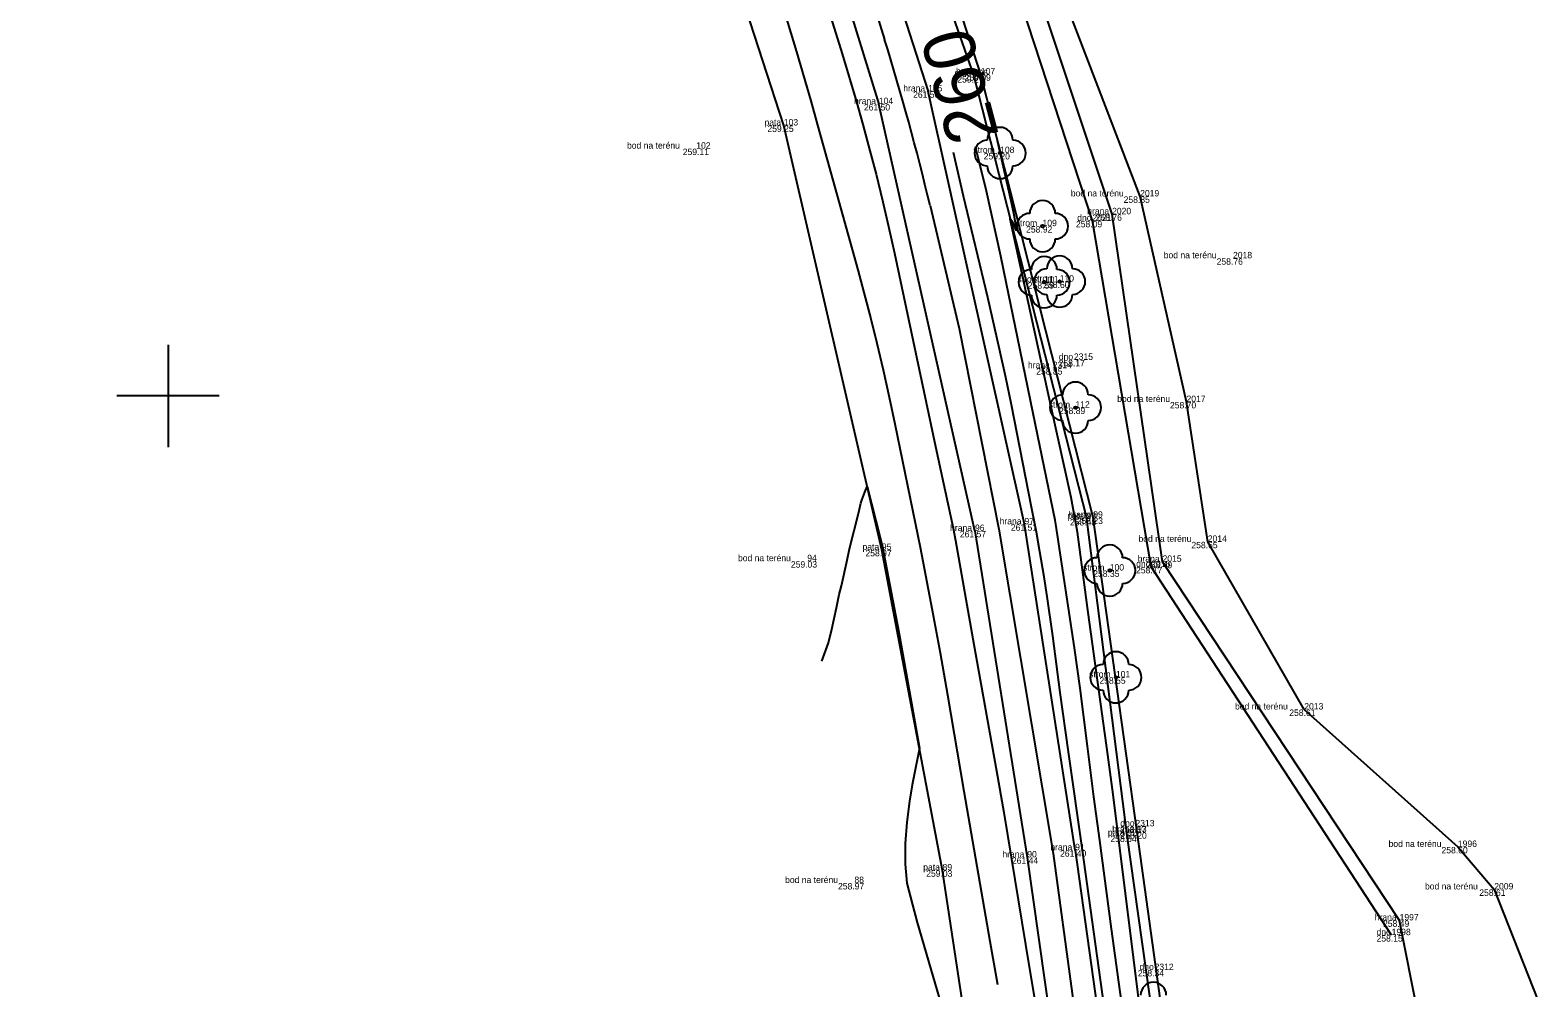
# Model space of a CAD drawing. Extents: x -567962 to -566460, y -1093720 to -1089838.
# Drawn here: x -567610.8 to -567493.1, y -1093446.2 to -1093371.4 of the extents above; entities that cross this region are included whole.
import ezdxf

# ---------------------------------------------------------------- set-up
doc = ezdxf.new("R2010")
doc.units = 0
for name, color, linetype in [('0_osa hráze', 7, 'Continuous'), ('bod_znacka', 7, 'Continuous'), ('cislo_bodu', 7, 'Continuous'), ('ctvercova_sit', 7, 'Continuous'), ('Doměření - kraj pole', 7, 'Continuous'), ('hlavni_vrst', 7, 'Continuous'), ('hrana_L', 7, 'Continuous'), ('kod_bodu', 7, 'Continuous'), ('norm_vrst', 7, 'Continuous'), ('Popis_hl_vrs', 7, 'Continuous'), ('stromy', 7, 'Continuous'), ('vyska_bodu', 7, 'Continuous')]:
    doc.layers.add(name, color=color, linetype=linetype)

msp = doc.modelspace()

# ---------------------------------------------------------------- linework, layer by layer
at = {"layer": '0_osa hráze'}
for points in [[(-567550.67, -1093350.89), (-567544.08, -1093372.16)], [(-567540.53, -1093385.13), (-567538.25, -1093394.72), (-567535.17, -1093410.4), (-567530.93, -1093435.73), (-567525.97, -1093472.15), (-567525.38, -1093480.07)]]:
    msp.add_lwpolyline(points, dxfattribs=at)
msp.add_arc((-567735.11, -1093431.38), 200, 13.3699, 17.225, dxfattribs=at)
at = {"layer": 'bod_znacka'}
for p, q in [((-567537.12, -1093375.03), (-567537.12, -1093375.03)), ((-567536.56, -1093374.89), (-567536.56, -1093374.89)), ((-567540.68, -1093376.22), (-567540.68, -1093376.22)), ((-567544.52, -1093377.21), (-567544.52, -1093377.21)), ((-567551.94, -1093378.88), (-567551.94, -1093378.88)), ((-567558.77, -1093380.69), (-567558.77, -1093380.69)), ((-567535.06, -1093381.03), (-567535.06, -1093381.03)), ((-567524.13, -1093384.42), (-567524.13, -1093384.42)), ((-567527.86, -1093386.33), (-567527.86, -1093386.33)), ((-567526.32, -1093385.81), (-567526.32, -1093385.81)), ((-567531.75, -1093386.74), (-567531.75, -1093386.74)), ((-567516.88, -1093389.25), (-567516.88, -1093389.25)), ((-567531.62, -1093391.12), (-567531.62, -1093391.12)), ((-567530.41, -1093391.07), (-567530.41, -1093391.07)), ((-567530.95, -1093397.83), (-567530.95, -1093397.83)), ((-567529.3, -1093397.18), (-567529.3, -1093397.18)), ((-567520.51, -1093400.47), (-567520.51, -1093400.47)), ((-567529.18, -1093400.91), (-567529.18, -1093400.91)), ((-567533.16, -1093410.02), (-567533.16, -1093410.02)), ((-567528.3, -1093409.61), (-567528.3, -1093409.61)), ((-567527.79, -1093409.5), (-567527.79, -1093409.5)), ((-567537.02, -1093410.54), (-567537.02, -1093410.54)), ((-567544.29, -1093412.02), (-567544.29, -1093412.02)), ((-567518.85, -1093411.39), (-567518.85, -1093411.39)), ((-567550.11, -1093412.9), (-567550.11, -1093412.9)), ((-567523.26, -1093413.35), (-567523.26, -1093413.35)), ((-567522.38, -1093412.95), (-567522.38, -1093412.95)), ((-567526.5, -1093413.63), (-567526.5, -1093413.63)), ((-567526.02, -1093421.97), (-567526.02, -1093421.97)), ((-567511.32, -1093424.48), (-567511.32, -1093424.48)), ((-567524.5, -1093433.6), (-567524.5, -1093433.6)), ((-567525.14, -1093434.33), (-567525.14, -1093434.33)), ((-567524.37, -1093434.07), (-567524.37, -1093434.07)), ((-567529.2, -1093435.47), (-567529.2, -1093435.47)), ((-567499.33, -1093435.21), (-567499.33, -1093435.21)), ((-567539.55, -1093437.04), (-567539.55, -1093437.04)), ((-567532.94, -1093436.03), (-567532.94, -1093436.03)), ((-567546.43, -1093438.03), (-567546.43, -1093438.03)), ((-567496.49, -1093438.53), (-567496.49, -1093438.53)), ((-567503.88, -1093440.95), (-567503.88, -1093440.95)), ((-567504.5, -1093442.1), (-567504.5, -1093442.1)), ((-567523, -1093444.82), (-567523, -1093444.82))]:
    msp.add_line(p, q, dxfattribs=at)
at = {"layer": 'ctvercova_sit'}
for points in [[(-567600, -1093396), (-567600, -1093404)], [(-567596, -1093400), (-567604, -1093400)]]:
    msp.add_lwpolyline(points, dxfattribs=at)
at = {"layer": 'Doměření - kraj pole'}
for points in [[(-567511.32, -1093424.48), (-567518.85, -1093411.39), (-567520.51, -1093400.47), (-567524.13, -1093384.42), (-567533.3, -1093360.45), (-567540.81, -1093336.06), (-567555.22, -1093294.34), (-567607.1, -1093144.72), (-567617.83, -1093113.35), (-567634.56, -1093065.71), (-567666.8, -1092973.41), (-567707.16, -1092860.34), (-567710.41, -1092851.09), (-567718.35, -1092825.43), (-567724.94, -1092789.73), (-567726.76, -1092756.76), (-567722.48, -1092688.96)], [(-567511.32, -1093424.48), (-567499.33, -1093435.21), (-567496.49, -1093438.53), (-567493.09, -1093447.18), (-567494.5, -1093456.59), (-567505.65, -1093469.6), (-567507.9, -1093475.55), (-567510.24, -1093490.41)]]:
    msp.add_lwpolyline(points, dxfattribs=at)
at = {"layer": 'hlavni_vrst'}
for points in [[(-567552.09, -1093369.36), (-567550.96, -1093373.14), (-567549.84, -1093376.95), (-567549.3, -1093378.86), (-567546.17, -1093390.14), (-567545.69, -1093391.91), (-567545.15, -1093393.97), (-567544.67, -1093395.88), (-567544.18, -1093397.96), (-567543.71, -1093400.09), (-567543.27, -1093402.17), (-567541.47, -1093410.93), (-567541.3, -1093411.8), (-567540.36, -1093416.73), (-567539.74, -1093420.06), (-567539.16, -1093423.34), (-567537.9, -1093430.85), (-567535.86, -1093442.57), (-567535.26, -1093445.96)], [(-567525.41, -1093448.61), (-567526.37, -1093441.6), (-567527.28, -1093434.7), (-567527.74, -1093431.31), (-567528.24, -1093427.34), (-567528.81, -1093422.82), (-567529.25, -1093419.66), (-567530.23, -1093413.11), (-567530.71, -1093410.02), (-567530.77, -1093409.69), (-567532.3, -1093402.26), (-567533.88, -1093394.53), (-567534.56, -1093391.25), (-567535.01, -1093389.08), (-567536.13, -1093384.01), (-567536.98, -1093380.54)]]:
    msp.add_lwpolyline(points, dxfattribs=at)
at = {"layer": 'hrana_L'}
for p, q in [((-567547.59, -1093345.05), (-567537.12, -1093375.03)), ((-567536.56, -1093374.89), (-567546.32, -1093344.74)), ((-567550.25, -1093346.34), (-567540.68, -1093376.22)), ((-567553.65, -1093347.55), (-567544.52, -1093377.21)), ((-567551.94, -1093378.88), (-567561.12, -1093350.53)), ((-567537.12, -1093375.03), (-567528.3, -1093409.61)), ((-567527.79, -1093409.5), (-567536.56, -1093374.89)), ((-567533.16, -1093410.02), (-567540.68, -1093376.22)), ((-567537.02, -1093410.54), (-567544.52, -1093377.21)), ((-567544.29, -1093412.02), (-567551.94, -1093378.88)), ((-567529.2, -1093435.47), (-567533.16, -1093410.02)), ((-567525.14, -1093434.33), (-567528.3, -1093409.61)), ((-567524.37, -1093434.07), (-567527.79, -1093409.5)), ((-567537.02, -1093410.54), (-567532.94, -1093436.03)), ((-567539.55, -1093437.04), (-567544.29, -1093412.02)), ((-567521.13, -1093462.82), (-567525.14, -1093434.33)), ((-567520.34, -1093462.89), (-567524.37, -1093434.07)), ((-567529.2, -1093435.47), (-567525.27, -1093463.58)), ((-567535.31, -1093465.11), (-567539.55, -1093437.04)), ((-567532.94, -1093436.03), (-567528.96, -1093464.11))]:
    msp.add_line(p, q, dxfattribs=at)
for points in [[(-567504.5, -1093442.1), (-567523.26, -1093413.35), (-567527.86, -1093386.33), (-567536.4, -1093360.17), (-567544.7, -1093335.63), (-567557.74, -1093295.13), (-567579.04, -1093235.03), (-567610.15, -1093146.43), (-567637.79, -1093066.78), (-567669.86, -1092975.82), (-567712.89, -1092852.93), (-567721.73, -1092825.85), (-567728.15, -1092790.55), (-567729.9, -1092755.99), (-567725.95, -1092688.52)], [(-567512.79, -1093499.42), (-567512.53, -1093490.77), (-567515.14, -1093473.2), (-567516.86, -1093463), (-567517.05, -1093457.43), (-567510.86, -1093456.87), (-567507.33, -1093455.1), (-567502.54, -1093450.69), (-567502.42, -1093448.31), (-567503.88, -1093440.95), (-567522.38, -1093412.95), (-567526.32, -1093385.81), (-567534.77, -1093360.4), (-567542.63, -1093336.01), (-567576.2, -1093233.72), (-567608.17, -1093145.58), (-567635.77, -1093066.14), (-567667.57, -1092974.74), (-567711.16, -1092852.65), (-567720.26, -1092825.93), (-567727.08, -1092790.56), (-567728.5, -1092756.42), (-567723.8, -1092688.57)]]:
    msp.add_lwpolyline(points, dxfattribs=at)
at = {"layer": 'norm_vrst'}
for points in [[(-567551.98, -1093358.49), (-567547.4, -1093373.28), (-567546.27, -1093377.03), (-567545.77, -1093378.81), (-567545.22, -1093380.87), (-567544.74, -1093382.67), (-567544.23, -1093384.74), (-567543.76, -1093386.77), (-567543.3, -1093388.86), (-567540.09, -1093403.95), (-567538.72, -1093410.31), (-567538.53, -1093411.29), (-567537.1, -1093419.41), (-567535.33, -1093429.28), (-567534.77, -1093432.53), (-567532.79, -1093444.58), (-567531.26, -1093453.73)], [(-567523.96, -1093449.25), (-567526.24, -1093431.12), (-567526.64, -1093428.01), (-567528.19, -1093416.9), (-567529.01, -1093410.64), (-567529.52, -1093407.94), (-567531.11, -1093400.75), (-567534.27, -1093386.19), (-567534.27, -1093386.14), (-567534.21, -1093386.22), (-567534.15, -1093386.33), (-567533.82, -1093387.06), (-567533.79, -1093387.03), (-567533.78, -1093386.94), (-567533.96, -1093385.88), (-567534.11, -1093385.13), (-567534.61, -1093382.94), (-567535.27, -1093380.09)], [(-567526.68, -1093449.51), (-567528.13, -1093439.02), (-567528.63, -1093435.47), (-567529.73, -1093427.79), (-567530.37, -1093423.16), (-567530.95, -1093418.74), (-567531.38, -1093415.67), (-567531.63, -1093414.11), (-567531.95, -1093412.18), (-567532.23, -1093410.64), (-567532.6, -1093408.67), (-567534.17, -1093400.68), (-567534.62, -1093398.55), (-567535.1, -1093396.34), (-567536.03, -1093392.32), (-567537.91, -1093384.39), (-567538.7, -1093381)], [(-567548.97, -1093420.71), (-567548.46, -1093419.28), (-567548.2, -1093418.2), (-567547.82, -1093416.54), (-567547.61, -1093415.49), (-567547.45, -1093414.82), (-567547.01, -1093412.81), (-567546.81, -1093411.94), (-567546.12, -1093409.18), (-567545.93, -1093408.37), (-567545.85, -1093408.13), (-567545.62, -1093407.52), (-567545.43, -1093407.08), (-567544.76, -1093409.72), (-567544.25, -1093411.78), (-567543.55, -1093415.33), (-567542.97, -1093418.44), (-567542.14, -1093423.09), (-567541.36, -1093427.51), (-567541.92, -1093430.37), (-567542.12, -1093431.65), (-567542.34, -1093433.29), (-567542.46, -1093434.95), (-567542.47, -1093436.56), (-567542.33, -1093438.03), (-567541.9, -1093439.73), (-567541.54, -1093441.11), (-567540.3, -1093445.29), (-567539.51, -1093448.05)]]:
    msp.add_lwpolyline(points, dxfattribs=at)
at = {"layer": 'stromy'}
for centre in [(-567535.06, -1093381.03), (-567531.75, -1093386.74), (-567531.62, -1093391.12), (-567530.41, -1093391.07), (-567529.18, -1093400.91), (-567526.5, -1093413.63), (-567526.02, -1093421.97)]:
    msp.add_circle(centre, 0.1, dxfattribs=at)
for centre, start, end in [((-567535.06, -1093380.03), 0, 180), ((-567536.06, -1093381.03), 90, 270), ((-567534.06, -1093381.03), 270, 90), ((-567535.06, -1093382.03), 180, 0), ((-567531.75, -1093385.74), 0, 180), ((-567532.75, -1093386.74), 90, 270), ((-567530.75, -1093386.74), 270, 90), ((-567531.75, -1093387.74), 180, 0), ((-567531.62, -1093390.12), 0, 180), ((-567531.41, -1093391.07), 90, 270), ((-567530.41, -1093390.07), 0, 180), ((-567529.41, -1093391.07), 270, 90), ((-567532.62, -1093391.12), 90, 270), ((-567530.62, -1093391.12), 270, 90), ((-567531.62, -1093392.12), 180, 0), ((-567530.41, -1093392.07), 180, 0), ((-567529.18, -1093399.91), 0, 180), ((-567530.18, -1093400.91), 90, 270), ((-567528.18, -1093400.91), 270, 90), ((-567529.18, -1093401.91), 180, 0), ((-567526.5, -1093412.63), 0, 180), ((-567527.5, -1093413.63), 90, 270), ((-567525.5, -1093413.63), 270, 90), ((-567526.5, -1093414.63), 180, 0), ((-567526.02, -1093420.97), 0, 180), ((-567527.02, -1093421.97), 90, 270), ((-567525.02, -1093421.97), 270, 90), ((-567526.02, -1093422.97), 180, 0), ((-567523.09, -1093446.78), 0, 180)]:
    msp.add_arc(centre, 1, start, end, dxfattribs=at)

# ---------------------------------------------------------------- texts
at = {"layer": 'cislo_bodu'}
for s, p in [('106', (-567537.12, -1093375.03)), ('107', (-567536.56, -1093374.89)), ('105', (-567540.68, -1093376.22)), ('104', (-567544.52, -1093377.21)), ('103', (-567551.94, -1093378.88)), ('102', (-567558.77, -1093380.69)), ('108', (-567535.06, -1093381.03)), ('2019', (-567524.13, -1093384.42)), ('2020', (-567526.32, -1093385.81)), ('109', (-567531.75, -1093386.74)), ('2021', (-567527.86, -1093386.33)), ('2018', (-567516.88, -1093389.25)), ('111', (-567531.62, -1093391.12)), ('110', (-567530.41, -1093391.07)), ('2315', (-567529.3, -1093397.18)), ('2314', (-567530.95, -1093397.83)), ('112', (-567529.18, -1093400.91)), ('2017', (-567520.51, -1093400.47)), ('96', (-567537.02, -1093410.54)), ('97', (-567533.16, -1093410.02)), ('98', (-567528.3, -1093409.61)), ('99', (-567527.79, -1093409.5)), ('2014', (-567518.85, -1093411.39)), ('94', (-567550.11, -1093412.9)), ('95', (-567544.29, -1093412.02)), ('2015', (-567522.38, -1093412.95)), ('100', (-567526.5, -1093413.63)), ('2016', (-567523.26, -1093413.35)), ('101', (-567526.02, -1093421.97)), ('2013', (-567511.32, -1093424.48)), ('2313', (-567524.5, -1093433.6)), ('93', (-567524.37, -1093434.07)), ('92', (-567525.14, -1093434.33)), ('1996', (-567499.33, -1093435.21)), ('90', (-567532.94, -1093436.03)), ('91', (-567529.2, -1093435.47)), ('89', (-567539.55, -1093437.04)), ('88', (-567546.43, -1093438.03)), ('2009', (-567496.49, -1093438.53)), ('1997', (-567503.88, -1093440.95)), ('1998', (-567504.5, -1093442.1)), ('2312', (-567523, -1093444.82))]:
    msp.add_text(s, height=0.5, dxfattribs=at).set_placement(p)
at = {"layer": 'kod_bodu'}
for s, p in [('pata', (-567538.63, -1093375.03)), ('hrana', (-567538.5, -1093374.89)), ('hrana', (-567542.62, -1093376.22)), ('hrana', (-567546.46, -1093377.21)), ('pata', (-567553.45, -1093378.88)), ('bod na terénu', (-567564.18, -1093380.69)), ('strom', (-567537.15, -1093381.03)), ('bod na terénu', (-567529.54, -1093384.42)), ('hrana', (-567528.26, -1093385.81)), ('strom', (-567533.84, -1093386.74)), ('dno', (-567529.04, -1093386.33)), ('bod na terénu', (-567522.29, -1093389.25)), ('strom', (-567533.71, -1093391.12)), ('strom', (-567532.5, -1093391.07)), ('dno', (-567530.48, -1093397.18)), ('hrana', (-567532.89, -1093397.83)), ('strom', (-567531.27, -1093400.91)), ('bod na terénu', (-567525.92, -1093400.47)), ('hrana', (-567538.96, -1093410.54)), ('hrana', (-567535.1, -1093410.02)), ('pata', (-567529.81, -1093409.61)), ('hrana', (-567529.73, -1093409.5)), ('bod na terénu', (-567524.26, -1093411.39)), ('bod na terénu', (-567555.52, -1093412.9)), ('pata', (-567545.8, -1093412.02)), ('hrana', (-567524.32, -1093412.95)), ('strom', (-567528.59, -1093413.63)), ('dno', (-567524.44, -1093413.35)), ('strom', (-567528.11, -1093421.97)), ('bod na terénu', (-567516.73, -1093424.48)), ('hrana', (-567526.31, -1093434.07)), ('dno', (-567525.68, -1093433.6)), ('pata', (-567526.65, -1093434.33)), ('bod na terénu', (-567504.74, -1093435.21)), ('hrana', (-567534.88, -1093436.03)), ('hrana', (-567531.14, -1093435.47)), ('pata', (-567541.06, -1093437.04)), ('bod na terénu', (-567551.84, -1093438.03)), ('bod na terénu', (-567501.9, -1093438.53)), ('hrana', (-567505.82, -1093440.95)), ('dno', (-567505.68, -1093442.1)), ('dno', (-567524.18, -1093444.82))]:
    msp.add_text(s, height=0.5, dxfattribs=at).set_placement(p)
at = {"layer": 'Popis_hl_vrs'}
msp.add_text('260', height=4, rotation=104.8639, dxfattribs=at).set_placement((-567535.14, -1093379.64))
at = {"layer": 'vyska_bodu'}
for s, p in [('259.27', (-567538.4, -1093375.53)), ('259.09', (-567537.83, -1093375.39)), ('261.50', (-567541.85, -1093376.72)), ('261.50', (-567545.69, -1093377.71)), ('259.25', (-567553.22, -1093379.38)), ('259.11', (-567559.83, -1093381.19)), ('259.20', (-567536.34, -1093381.53)), ('258.85', (-567525.42, -1093384.92)), ('258.09', (-567529.14, -1093386.83)), ('258.76', (-567527.6, -1093386.31)), ('258.92', (-567533.03, -1093387.24)), ('258.76', (-567518.16, -1093389.75)), ('258.59', (-567532.9, -1093391.62)), ('258.60', (-567531.69, -1093391.57)), ('258.85', (-567532.24, -1093398.33)), ('258.17', (-567530.49, -1093397.68)), ('258.70', (-567521.8, -1093400.97)), ('258.89', (-567530.46, -1093401.41)), ('261.51', (-567534.22, -1093410.52)), ('258.48', (-567529.61, -1093410.11)), ('258.23', (-567529.08, -1093410)), ('261.57', (-567538.2, -1093411.04)), ('258.97', (-567545.57, -1093412.52)), ('258.65', (-567520.13, -1093411.89)), ('259.03', (-567551.39, -1093413.4)), ('258.35', (-567527.79, -1093414.13)), ('258.17', (-567524.45, -1093413.85)), ('258.49', (-567523.67, -1093413.45)), ('258.55', (-567527.31, -1093422.47)), ('258.61', (-567512.49, -1093424.98)), ('258.17', (-567525.69, -1093434.1)), ('258.54', (-567526.45, -1093434.83)), ('258.20', (-567525.66, -1093434.57)), ('261.40', (-567530.38, -1093435.97)), ('258.60', (-567500.61, -1093435.71)), ('259.03', (-567540.83, -1093437.54)), ('261.44', (-567534.14, -1093436.53)), ('258.97', (-567547.71, -1093438.53)), ('258.61', (-567497.66, -1093439.03)), ('258.49', (-567505.17, -1093441.45)), ('258.15', (-567505.68, -1093442.6)), ('258.34', (-567524.31, -1093445.32))]:
    msp.add_text(s, height=0.5, dxfattribs=at).set_placement(p)

doc.saveas('drawing.dxf')
